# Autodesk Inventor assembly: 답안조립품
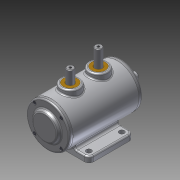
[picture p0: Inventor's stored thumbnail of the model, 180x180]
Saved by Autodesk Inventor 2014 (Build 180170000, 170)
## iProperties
Created: 2014-12
Part Number: 답안조립품
Document SubType Name: Assembly
Designer: Owner
Author: Owner
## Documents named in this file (10)
- C:\Users\Owner\Desktop\441223V1020\답안조립품.iam
- C:\Users\Owner\Desktop\441223V1020\본체.ipt
- C:\Users\Owner\Desktop\441223V1020\M4-소켓머리.ipt
- C:\Users\Owner\Desktop\441223V1020\뒷커버.ipt
- C:\Users\Owner\Desktop\441223V1020\베어링 6203.ipt
- C:\Users\Owner\Desktop\441223V1020\부시.ipt
- C:\Users\Owner\Desktop\441223V1020\슬라이더.ipt
- C:\Users\Owner\Desktop\441223V1020\앞커버.ipt
- C:\Users\Owner\Desktop\441223V1020\오일실.ipt
- C:\Users\Owner\Desktop\441223V1020\축.ipt
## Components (11 placed, 3 different names)
1. 7-베어링 6203:1
2. 8-오일실:1
3. 7-베어링 6203:2
4. 9-M4-소켓머리:2
5. 9-M4-소켓머리:3
6. 9-M4-소켓머리:4
7. 9-M4-소켓머리:5
8. 9-M4-소켓머리:1
9. 9-M4-소켓머리:6
10. 9-M4-소켓머리:7
11. 9-M4-소켓머리:8
